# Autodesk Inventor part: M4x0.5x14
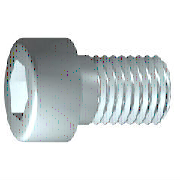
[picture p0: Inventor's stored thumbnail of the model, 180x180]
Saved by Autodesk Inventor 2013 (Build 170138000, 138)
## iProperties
IsCustomPart: 1
Company: 한국ATC센터
Created: 2009-02
Part Number: M4x0.5x14
Material: 강, 연강
Description: 6각머리 태핑 나사
Document SubType Name: Modeling
Standard: KS B 1003
Designer: KYOUNG IL JANG
Standards Organization: KS
Language: ko-KR
Size Designation: M 4 x 16
Categories: <MemberInstance><Categories><Category DisplayName="조임쇠" InternalName="e4da775c-781d-43d5-af7c-5136215cf5a6" Mnemonic="FSTN"><Category DisplayName="볼트" InternalN
Density: 7.86 g/cm^3
Mass: 2.43327 g
Surface Area: 3.56234 cm^2
Volume: 0.309576 cm^3
Vendor: CBT Solutions
Author: KYOUNG IL JANG
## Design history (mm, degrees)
sketch "스케치1"
  geometry: L1 (-1, 0)-(16, 0); L2 (16, 0)-(16, 2); L3 (16, 2)-(1.75, 2); L4 (1.75, 2)-(1.32, 2); L5 (1.32, 2)-(0, 2); L6 (0, 2)-(0, 3.5); L7 (0, 3.5)-(-4, 3.5); L8 (-4, 3.5)-(-4, 1.732); L9 (-4, 1.732)-(-2, 1.732); L10 (-2, 1.732)-(-1, 0); L11 (-8, 0)-(20, 0) reference; L12 (0, -0.7)-(0, 4.2) reference; L13 (1.75, 2)-(0, 2)
  constraints: 22 end point, 6 parallel, 2 collinear, 2 perpendicular, 1 horizontal, 1 point on line
  dimensions: "d1" = 14.25 distance from line of L3.end L2 (= GEL); "d2" = 0.42952 distance of L4.end L3.end (computed from GAL); "d3" = 4 distance between parallel lines of L8 L6 (= KOH); "d4" = 2 distance of L8.end L9.end (= INTI); "d5" = 60 deg angle of L10 L1; "d6" = 4 diameter of L3 L1 (= GD); "d7" = 4 diameter of L5 L1 (= BDM); "d8" = 3.4641 diameter of L9 L1 (= 1.1547 x SW); "d9" = 7 diameter of L7 L1 (= KOD); "d26" = 16 distance between parallel lines of L12 L2 (= NLG)
revolve "본체" sketch "스케치1" stored, may be unused: angle "d10" = 90 deg
sketch "스케치2"
  geometry: L1 (0, -4.9)-(0, 4.9) reference; L2 (-4.9, 0)-(4.9, 0) reference; L3 (1.732, 0)-(0.866, -1.5); L4 (0.866, -1.5)-(-0.866, -1.5); L5 (-0.866, -1.5)-(-1.732, 0); L6 (-1.732, 0)-(-0.866, 1.5); L7 (-0.866, 1.5)-(0.866, 1.5); L8 (0.866, 1.5)-(1.732, 0); 2 further points
  constraints: 12 end point, 1 coincident, 1 horizontal alignment, 1 point on line, 12 other
extrude "슬롯" join sketch "스케치2" stored distance "d11" = 10; taper "d12" = 0 deg
workplane "Work Plane1"
fillet "Fillet2" dims "d30" = 0.1 (= R)
sketch "스케치4"
  geometry: C1 r 2.574 at (0, 0); 1 further point
  constraints: 1 centre point, 1 coincident
extrude "돌출3" cut sketch "스케치4" distance "d31" = 2; taper "d32" = 0 deg
chamfer "모따기3" distance "d33" = 0.4; stored, may be unused: second distance "d34" = 2, angle "d35" = 45 deg
body "Solid1"
fillet "모깎기1" dims "d17" = 0.4 (= RR)
feature "스레드" dims "d13" = 14.25 (= GEL), "d14" = 0
chamfer "모따기1" distance "d15" = 0.42941 (= -0.5 x SPD + 0.5 x GD); stored, may be unused: second distance "d16" = 0.42941 (= GUL), angle "d27" = 45 deg
other parameters: "GD" = 4 (= NND) [user parameter; used in 2 equation terms], "NLG" = 16 [user parameter; used in 1 equation term], "GEL" = 14.25 [user parameter; used in 2 equation terms], "KOD" = 7 [user parameter; used in 1 equation term], "KOH" = 4 [user parameter; used in 1 equation term], "INTI" = 2 [user parameter; used in 1 equation term], "GAL" = 0.42941 (= 0.61345 x PTC) [user parameter; used in 1 equation term], "GUL" = 0.42941 (= 0.61345 x PTC) [user parameter; used in 1 equation term], "BDM" = 4 (= NND) [user parameter; used in 1 equation term], "SW" = 3 [user parameter; used in 2 equation terms], "RR" = 0.4 [user parameter; used in 1 equation term], "SPD" = 3.14117 (= NND - 1.2269 x PTC) [user parameter; used in 1 equation term], "d19" = 0, "d28" = 0, "d29" = 0, "R" = 0.1 [user parameter; used in 1 equation term], "PHH" = 0.2 [user parameter], "GD1" = 3.14117 (= THREADDIA - 1.2269 x PTC) [user parameter], "THREADDIA" = 4 [user parameter; used in 1 equation term], "FAWI" = 45 deg [user parameter], "TPU" = 14.28571 (computed from PTC) [user parameter], "PTC" = 0.7 [user parameter; used in 5 equation terms], "NND" = 4 [user parameter; used in 3 equation terms], "TOA" = 30 deg [user parameter], "E0" = 3.465 (= 1.155 x SW) [user parameter]
